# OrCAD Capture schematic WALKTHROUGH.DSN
size A; title: PSpice Walkthrough; rev: A; company: EMA Design Automation; note: EMA-12345678; note: 225 Tech Park Dr; note: Rochester, NY
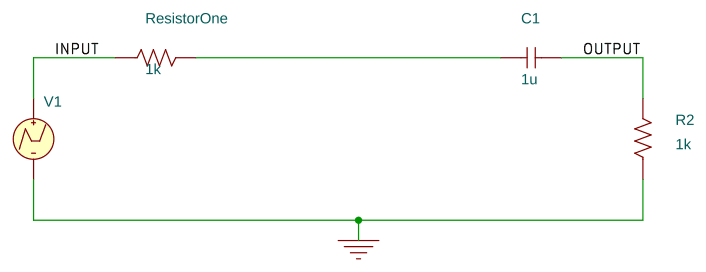
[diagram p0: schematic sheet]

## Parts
C1  1u  [RAD/CK05]
R2  1k  [AXRC05]
ResistorOne  1k  [AXRC05]
V1  VPWL_GENERIC

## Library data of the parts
C1 = C: AppProp: InductiveSlave:;SRF:;PrevCap:1u;PrevESL:; IC: 0; Tolerance: 5
R2 ResistorOne = R
V1 = VPWL_GENERIC: AppProp: Finite_reps$POINTS_TYPE_PWL$0$0; FIRST_NPAIRS: 1m 2m 2m 0 3m 3m 4m 1m 5m 0; PSpiceTemplate: V^@REFDES %+ %- ?DC|DC @DC| ?AC|AC @AC| PWL ?TSF|TIME_SCALE_FACTOR=@TSF| ?VSF|VALUE_SCALE_FACTOR=@VSF| ?REPEAT_VALUE| \n+ REPEAT FOR @REPEAT_VALUE| \n+ @FIRST_NPAIRS ?SECOND_NPAIRS|\n+ @SECOND_NPAIRS ?THIRD_NPAIRS/\n+ @THIRD_NPAIRS/| ?REPEAT_VALUE| \n+ ENDREPEAT|; REPEAT_VALUE: 2

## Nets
0: R2.1 V1.2(-)
INPUT: ResistorOne.1 V1.1(+)
OUTPUT: C1.2 R2.2
N00358: C1.1 ResistorOne.2
